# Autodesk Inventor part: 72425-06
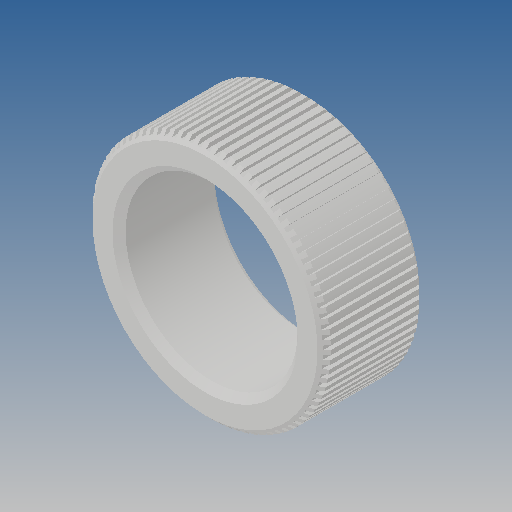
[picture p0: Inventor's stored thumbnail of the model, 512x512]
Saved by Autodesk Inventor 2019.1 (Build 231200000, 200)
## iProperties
Created: 2012-10
Part Number: 72425-06
Material: Ogólny
Document SubType Name: Modeling
Designer: CADENGINEERING4
Density: 1 g/cm^3
Appearance: Domyślna
Author: CADENGINEERING4
Revision Number: ÈÎºÎ
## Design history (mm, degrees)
feature "ÊäÈë1"
node "Bryła1"
